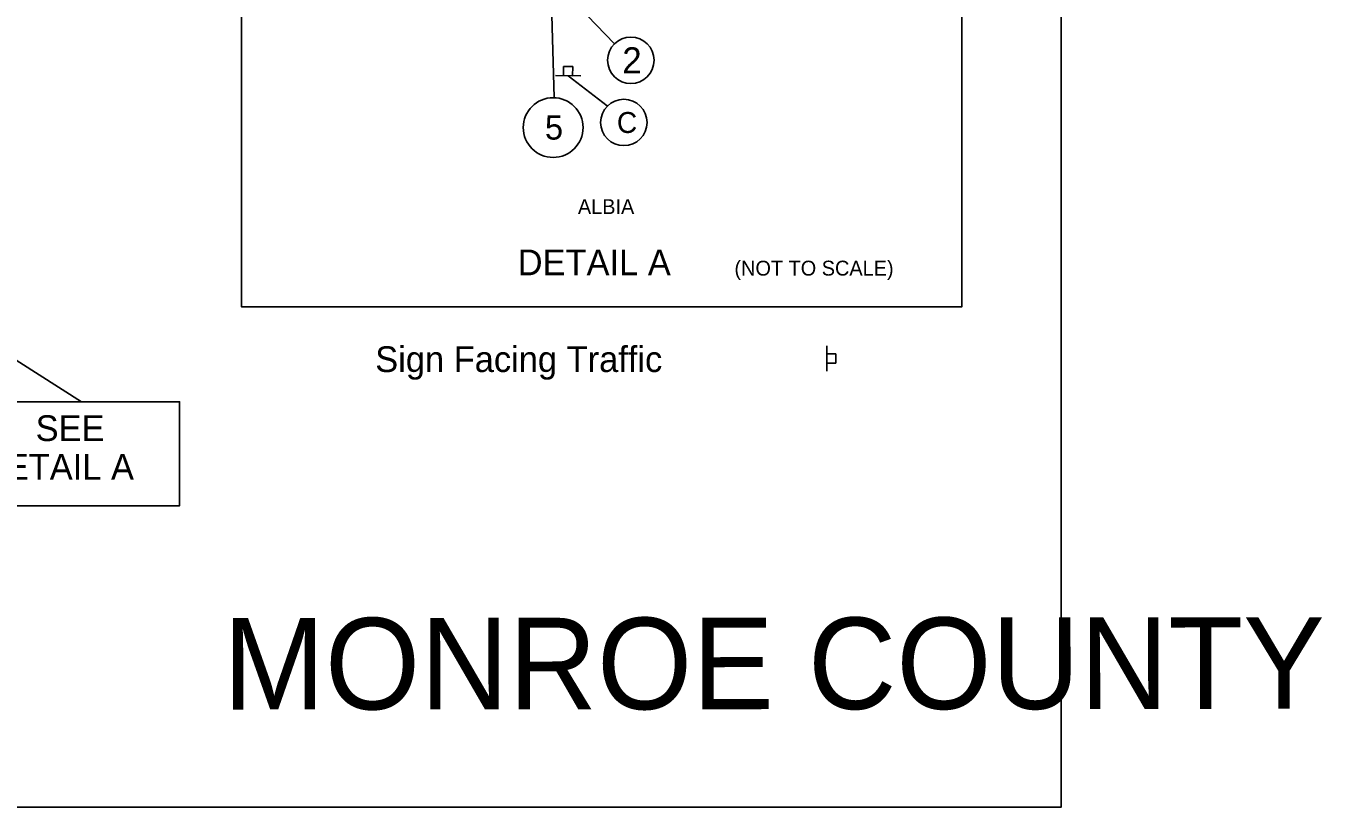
# Model space of a CAD drawing. Extents: x 10133 to 81668, y 5524 to 11018.
# Drawn here: x 15963 to 17095, y 7924 to 8607 of the extents above; entities that cross this region are included whole.
import ezdxf

# ---------------------------------------------------------------- set-up
doc = ezdxf.new("R2010")
doc.units = 0
for name, color, linetype in [('Default', 7, 'Continuous'), ('DisBoundDim', 7, 'Continuous'), ('DisCLMLOR', 7, 'Continuous'), ('DisCLMLSUR', 7, 'Continuous'), ('dsnShtPlotShapeBatchPrint', 7, 'Continuous'), ('Level 3', 7, 'Continuous'), ('trf_Signal_(Temp)_Layout', 7, 'Continuous'), ('trf_SignNumber_Text', 7, 'Continuous')]:
    doc.layers.add(name, color=color, linetype=linetype)

msp = doc.modelspace()

# ---------------------------------------------------------------- linework, layer by layer
at = {"layer": 'Default'}
msp.add_circle((16423.5, 8518), 26.1, dxfattribs=at)
at = {"layer": 'DisBoundDim'}
for p, q in [((16425.4, 8563.4), (16447.6, 8563.3)), ((16432.5, 8563.4), (16432.6, 8571.4)), ((16432.6, 8571.4), (16440.6, 8571.3)), ((16440.5, 8563.3), (16440.6, 8571.3)), ((16662.6, 8305.2), (16662.6, 8327.3)), ((16662.6, 8320.2), (16670.6, 8320.2)), ((16670.6, 8312.2), (16670.6, 8320.2)), ((16662.6, 8312.2), (16670.6, 8312.2))]:
    msp.add_line(p, q, dxfattribs=at)
at = {"layer": 'DisCLMLOR'}
for p, q in [((16432.5, 8563.4), (16432.6, 8571.4)), ((16432.5, 8563.4), (16432.6, 8571.4)), ((16432.5, 8563.4), (16432.6, 8571.4)), ((16432.5, 8563.4), (16432.6, 8571.4)), ((16440.5, 8563.3), (16432.5, 8563.4)), ((16440.5, 8563.3), (16432.5, 8563.4)), ((16440.5, 8563.3), (16432.5, 8563.4)), ((16440.5, 8563.3), (16432.5, 8563.4)), ((16432.6, 8571.4), (16440.6, 8571.3)), ((16432.6, 8571.4), (16440.6, 8571.3)), ((16432.6, 8571.4), (16440.6, 8571.3)), ((16432.6, 8571.4), (16440.6, 8571.3)), ((16440.6, 8571.3), (16440.5, 8563.3)), ((16440.6, 8571.3), (16440.5, 8563.3)), ((16440.6, 8571.3), (16440.5, 8563.3)), ((16440.6, 8571.3), (16440.5, 8563.3)), ((16670.6, 8320.2), (16662.6, 8320.2)), ((16662.6, 8320.2), (16662.6, 8312.2)), ((16670.6, 8320.2), (16662.6, 8320.2)), ((16662.6, 8320.2), (16662.6, 8312.2)), ((16670.6, 8320.2), (16662.6, 8320.2)), ((16662.6, 8320.2), (16662.6, 8312.2)), ((16670.6, 8320.2), (16662.6, 8320.2)), ((16662.6, 8320.2), (16662.6, 8312.2)), ((16670.6, 8312.2), (16670.6, 8320.2)), ((16670.6, 8312.2), (16670.6, 8320.2)), ((16670.6, 8312.2), (16670.6, 8320.2)), ((16670.6, 8312.2), (16670.6, 8320.2)), ((16662.6, 8312.2), (16670.6, 8312.2)), ((16662.6, 8312.2), (16670.6, 8312.2)), ((16662.6, 8312.2), (16670.6, 8312.2)), ((16662.6, 8312.2), (16670.6, 8312.2))]:
    msp.add_line(p, q, dxfattribs=at)
at = {"layer": 'DisCLMLSUR'}
for p, q in [((16433, 8637.2), (16477, 8591.2)), ((16436.5, 8563.3), (16470.8, 8536.9))]:
    msp.add_line(p, q, dxfattribs=at)
at = {"layer": 'dsnShtPlotShapeBatchPrint'}
msp.add_lwpolyline([(16424.3, 8544.3), (16421.9, 8626.6), (16421.9, 8626.9), (16419.9, 8663.6), (16418.8, 8681.7), (16418.7, 8685.1), (16417.9, 8762.7)], dxfattribs=at)
at = {"layer": 'Level 3'}
msp.add_lwpolyline([(13732.5, 9944), (16867.5, 9944), (16867.5, 7924), (13732.5, 7924)], close=True, dxfattribs=at)
at = {"layer": 'trf_Signal_(Temp)_Layout'}
msp.add_line((15820.2, 8399.6), (16011.3, 8278.4), dxfattribs=at)
for points in [[(16151.2, 9682.4), (16780.5, 9682.4), (16780.5, 8361.3), (16151.2, 8361.3)], [(15925.7, 8278.4), (16097, 8278.4), (16097, 8187.4), (15925.7, 8187.4)]]:
    msp.add_lwpolyline(points, close=True, dxfattribs=at)
at = {"layer": 'trf_SignNumber_Text'}
for centre in [(16491.4, 8576.8), (16485.2, 8522.5)]:
    msp.add_circle(centre, 20.3, dxfattribs=at)

# ---------------------------------------------------------------- texts
at = {"layer": 'Default'}
msp.add_text('5', height=21.3, dxfattribs=at).set_placement((16416.3, 8507.5))
for s, height, rotation, p in [('ALBIA', 13, 0.0279, (16445.1, 8442.4)), ('(NOT TO SCALE)', 13, 0.0279, (16581.9, 8388.6)), ('MONROE COUNTY', 80, 0.038, (16135, 8009.3))]:
    msp.add_text(s, height=height, rotation=rotation, dxfattribs=at).set_placement(p)
at = {"layer": 'DisCLMLSUR'}
for s, p in [('  DETAIL A', (16375.8, 8388.9)), ('Sign Facing Traffic', (16268, 8304.3)), (' SEE', (15962.9, 8244)), ('  DETAIL A', (15906.7, 8210.2))]:
    msp.add_text(s, height=22.5, dxfattribs=at).set_placement(p)
at = {"layer": 'trf_SignNumber_Text'}
for s, height, p in [('2', 22.8, (16483.9, 8565.4)), ('C', 18.3, (16479.2, 8513.3))]:
    msp.add_text(s, height=height, dxfattribs=at).set_placement(p)

doc.saveas('drawing.dxf')
